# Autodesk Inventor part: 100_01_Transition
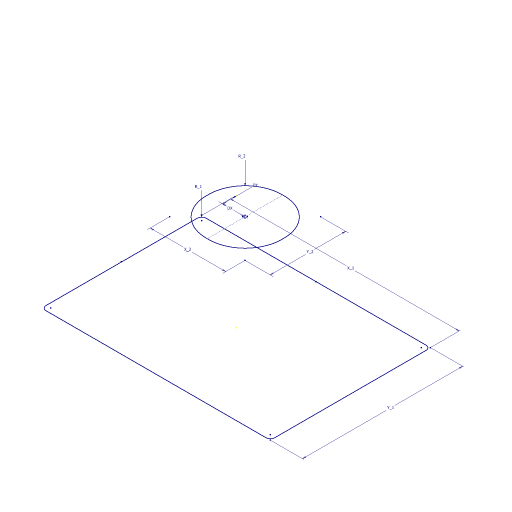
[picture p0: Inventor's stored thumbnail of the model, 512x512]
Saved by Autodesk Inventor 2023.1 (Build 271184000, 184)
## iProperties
Company: Fabian Stasiak CAD Consulting
Category: Autodesk® Inventor® Tutorial Series
Created: 2011-01
Part Number: 100_01_Transition
Material: Steel
Document SubType Name: Konstrukcja blachowa
Designer: F.Stasiak
Density: 7.85 g/cm^3
Sheet Metal Rule: Steel 1.5 mm/Straight
Sheet Metal Width: 0,000 mm
Sheet Metal Length: 0,000 mm
Sheet Metal Area: 0,000 mm^2
Appearance: Semi-Polished
Catalog Web Link: www.expertbooks.eu
Description: Transition
FLATAREA: =<FLAT PATTERN AREA>
Thickness: 1,500 mm
Author: F.Stasiak
Subject: Sheet Metal Design. Basic and Advanced techniques
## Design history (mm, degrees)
sketch "Szkic1"
  geometry: L1 (-240, -175)-(240, -175); L2 (250, -165)-(250, 165); L3 (240, 175)-(-240, 175); L4 (-250, 165)-(-250, -165); A1 r 10 centre (-240, 165) between (-240, 175) and (-250, 165); A2 r 10 centre (240, 165) between (250, 165) and (240, 175); A3 r 10 centre (240, -165) between (240, -175) and (250, -165); A4 r 10 centre (-240, -165) between (-250, -165) and (-240, -175); 6 further points
  constraints: 8 end point, 8 point on circle, 8 tangent, 6 point on line, 4 centre point, 3 equal radius, 2 midpoint, 2 parallel, 1 horizontal, 1 horizontal alignment, 1 perpendicular, 1 vertical alignment
  dimensions: "X_1" = 500 distance of point (-250, 175) point (250, 175); "Y_1" = 350 distance of point (250, 175) point (250, -175); "R_1" = 10 radius of A1
node "Płaszczyzna konstrukcyjna1"
sketch "Szkic2"
  geometry: L1 (47.5, 52.5)-(52.5, 52.5); L2 (132.5, -27.5)-(132.5, -32.5); L3 (52.5, -112.5)-(47.5, -112.5); L4 (-32.5, -32.5)-(-32.5, -27.5); L5 (50, 52.5)-(50, -112.5); A1 r 80 centre (47.5, -27.5) between (47.5, 52.5) and (-32.5, -27.5); A2 r 80 centre (52.5, -27.5) between (132.5, -27.5) and (52.5, 52.5); A3 r 80 centre (52.5, -32.5) between (52.5, -112.5) and (132.5, -32.5); A4 r 80 centre (47.5, -32.5) between (-32.5, -32.5) and (47.5, -112.5); 5 further points
  constraints: 10 end point, 8 point on circle, 8 tangent, 6 point on line, 4 centre point, 3 equal radius, 3 midpoint, 2 parallel, 1 horizontal, 1 perpendicular
  dimensions: "X_2" = 165 distance of point (132.5, -112.5) point (-32.5, -112.5); "Y_2" = 165 distance of point (132.5, 52.5) point (132.5, -112.5); "R_2" = 80 radius of A1; "DX" = 50 horizontal distance of point (0, 0) point (50, -30); "DY" = 30 vertical distance of point (50, -30) point (0, 0)
node "Bryła3"
other parameters: "Thickness" = 1.5 (derived), "WspółczynnikK" = 4.4, "BendRadius" = 1.5 (= Thickness), "BendReliefWidth" = 1.5 (= Thickness), "BendReliefDepth" = 0.75 (= 0.5 x Thickness), "CornerReliefSize" = 6 (= 4 x Thickness), "OdstępPołączenia" = 0.01, "MinimumRemnant" = 3 (= 2 x Thickness), "TransitionRadius" = 1.5 (= BendRadius), "JacobiRadiusSize" = 1.5 (= BendRadius), "GapSize" = 1.5 (= Thickness)
